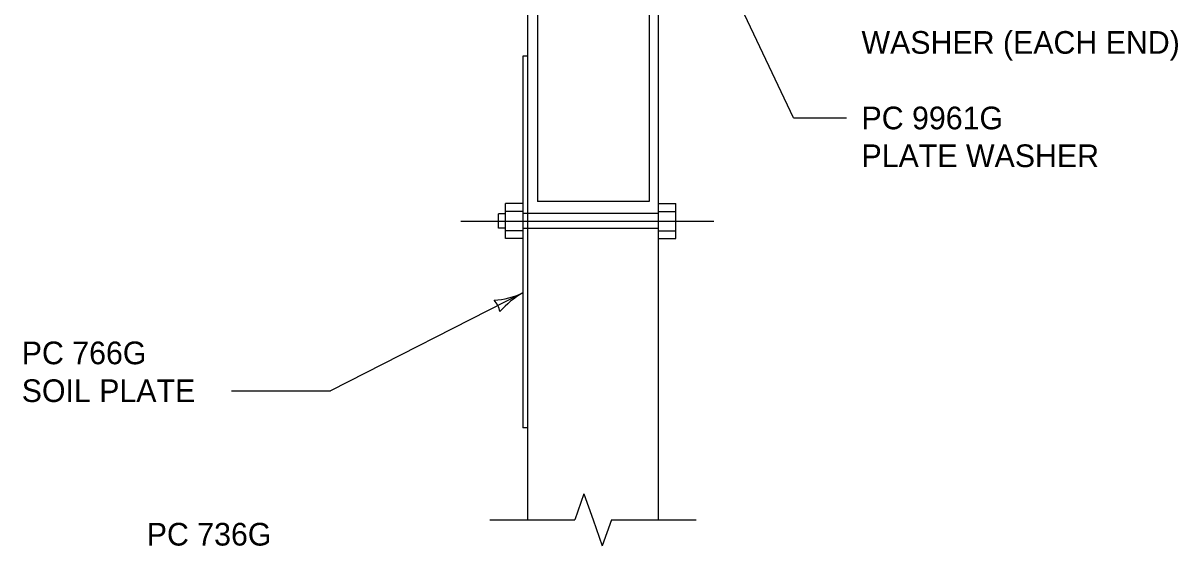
# Model space of a CAD drawing. Extents: x 49991.4 to 50021, y 49987.6 to 50011.4.
# Drawn here: x 50007.803 to 50010.859, y 49989.64 to 49991.023 of the extents above; entities that cross this region are included whole.
import ezdxf

# ---------------------------------------------------------------- set-up
doc = ezdxf.new("R2010")
doc.units = 0
for name, color, linetype in [('Level 1', 7, 'Continuous'), ('Level 2', 7, 'Continuous'), ('Level 3', 7, 'Continuous'), ('Level 4', 7, 'Continuous'), ('Level 5', 7, 'Continuous'), ('Level 6', 7, 'Continuous')]:
    doc.layers.add(name, color=color, linetype=linetype)

msp = doc.modelspace()

# ---------------------------------------------------------------- linework, layer by layer
at = {"layer": 'Level 1'}
for p, q in [((50009.125, 49990.5458), (50009.0791, 49990.5458)), ((50009.0791, 49990.4532), (50009.0791, 49990.5458)), ((50009.4845, 49990.5458), (50009.5305, 49990.5458)), ((50009.5305, 49990.4532), (50009.5305, 49990.5458)), ((50009.0791, 49990.5188), (50009.0608, 49990.5188)), ((50009.0608, 49990.4804), (50009.0608, 49990.5188)), ((50009.125, 49990.5251), (50009.0791, 49990.5251)), ((50009.4845, 49990.5251), (50009.5305, 49990.5251)), ((50009.0791, 49990.4804), (50009.0608, 49990.4804)), ((50009.125, 49990.4739), (50009.0791, 49990.4739)), ((50009.4845, 49990.4739), (50009.5305, 49990.4739)), ((50009.125, 49990.4532), (50009.0791, 49990.4532)), ((50009.4845, 49990.4532), (50009.5305, 49990.4532))]:
    msp.add_line(p, q, dxfattribs=at)
at = {"layer": 'Level 3'}
for points in [[(50009.8418, 49990.7723), (50009.5341, 49991.4226)], [(50009.8418, 49990.7723), (50009.9818, 49990.7723)], [(50009.125, 49990.3092), (50008.6166, 49990.0504)], [(50008.3546, 49990.0504), (50008.6166, 49990.0504)]]:
    msp.add_lwpolyline(points, dxfattribs=at)
for centre, radius, start, end in [((50009.0324, 49990.5113), 0.2223, 274.4343, 294.6178), ((50009.0107, 49990.251), 0.0548, 9.1171, 44.8395), ((50009.2408, 49990.107), 0.233, 119.8056, 139.0554)]:
    msp.add_arc(centre, radius, start, end, dxfattribs=at)
at = {"layer": 'Level 4'}
for p, q in [((50009.1384, 49989.7086), (50009.1384, 49991.2942)), ((50009.1638, 49991.2942), (50009.1638, 49990.5512)), ((50009.4593, 49991.2942), (50009.4593, 49990.5512)), ((50009.4845, 49989.7086), (50009.4845, 49991.2942)), ((50009.1384, 49990.9358), (50009.125, 49990.9358)), ((50009.125, 49990.9358), (50009.125, 49989.9521)), ((50009.4593, 49990.5512), (50009.1638, 49990.5512)), ((50009.4845, 49990.5191), (50009.125, 49990.5191)), ((50009.4845, 49990.4801), (50009.125, 49990.4801)), ((50009.1384, 49989.9521), (50009.125, 49989.9521))]:
    msp.add_line(p, q, dxfattribs=at)
at = {"layer": 'Level 5'}
msp.add_line((50008.9608, 49990.4995), (50009.6305, 49990.4995), dxfattribs=at)
at = {"layer": 'Level 6'}
for p, q in [((50009.287, 49989.7772), (50009.2627, 49989.7086)), ((50009.287, 49989.7772), (50009.3113, 49989.7086)), ((50009.0384, 49989.7086), (50009.2627, 49989.7086)), ((50009.3113, 49989.7086), (50009.3356, 49989.64)), ((50009.3599, 49989.7086), (50009.3356, 49989.64)), ((50009.3599, 49989.7086), (50009.5845, 49989.7086))]:
    msp.add_line(p, q, dxfattribs=at)

# ---------------------------------------------------------------- texts
at = {"layer": 'Level 2'}
for s, p in [('WASHER (EACH END)', (50010.0218, 49990.9423)), ('PC 9961G', (50010.0218, 49990.7423)), ('PLATE WASHER', (50010.0218, 49990.6423)), ('PC 766G', (50007.7989, 49990.1204)), ('SOIL PLATE', (50007.7989, 49990.0204)), ('PC 736G', (50008.1298, 49989.6404))]:
    msp.add_text(s, height=0.06, dxfattribs=at).set_placement(p)

doc.saveas('drawing.dxf')
